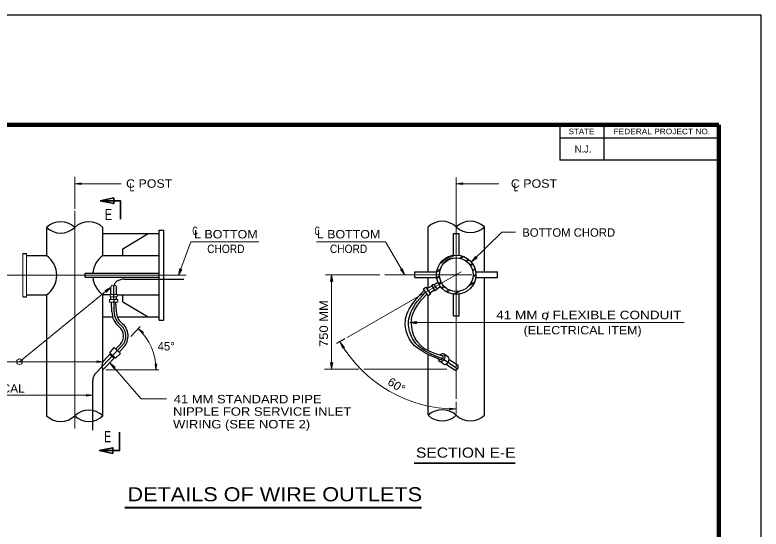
# Model space of a CAD drawing. Extents: x 312601.858 to 312602.699, y 144420.109 to 144420.704.
# Drawn here: x 312602.4337 to 312602.6988, y 144420.5208 to 144420.7035 of the extents above; entities that cross this region are included whole.
import ezdxf
from ezdxf.enums import TextEntityAlignment as Align

# ---------------------------------------------------------------- set-up
doc = ezdxf.new("R2010")
doc.units = 0
doc.header["$LTSCALE"] = 0.0012
doc.linetypes.add('LONG_DASH_SHORT_DASH', pattern=[9.9, 6, -1.2, 1.5, -1.2])
doc.linetypes.add('LONG_DASHED', pattern=[7.5, 6, -1.5])
for name, color, linetype, lineweight in [('1', 7, 'Continuous', 25), ('2', 7, 'Continuous', 25), ('39', 7, 'Continuous', 13), ('61', 7, 'Continuous', 25)]:
    doc.layers.add(name, color=color, linetype=linetype, lineweight=lineweight)

msp = doc.modelspace()

# ---------------------------------------------------------------- hatches: boundary and pattern name
at = {"layer": '39'}
for points in [[(312602.5975, 144420.6173), (312602.5979, 144420.6172), (312602.5959, 144420.6158), (312602.5974, 144420.6177)], [(312602.4926, 144420.613), (312602.493, 144420.6131), (312602.4918, 144420.611), (312602.4923, 144420.6134)], [(312602.5462, 144420.609), (312602.5458, 144420.6088), (312602.5462, 144420.6112), (312602.5466, 144420.6088)], [(312602.5462, 144420.609), (312602.5458, 144420.6088), (312602.5462, 144420.6112), (312602.5466, 144420.6088)], [(312602.5711, 144420.6131), (312602.5713, 144420.6134), (312602.5722, 144420.6112), (312602.5707, 144420.6131)], [(312602.4661, 144420.6054), (312602.4657, 144420.6056), (312602.4678, 144420.6068), (312602.4662, 144420.605)], [(312602.5762, 144420.5942), (312602.5764, 144420.5938), (312602.574, 144420.5942), (312602.5764, 144420.5946)], [(312602.5504, 144420.5853), (312602.5502, 144420.585), (312602.5493, 144420.5872), (312602.5508, 144420.5853)], [(312602.5504, 144420.5853), (312602.5502, 144420.585), (312602.5493, 144420.5872), (312602.5508, 144420.5853)], [(312602.5462, 144420.5798), (312602.5466, 144420.58), (312602.5462, 144420.5776), (312602.5458, 144420.58)], [(312602.5883, 144420.5635), (312602.5881, 144420.5638), (312602.5905, 144420.5635), (312602.5881, 144420.5632)]]:
    msp.add_hatch(color=256, dxfattribs=at).paths.add_polyline_path(points)

# ---------------------------------------------------------------- linework, layer by layer
at = {"layer": '1', "lineweight": 13}
for p, q in [((312602.455, 144420.6346), (312602.455, 144420.646)), ((312602.5905, 144420.6458), (312602.5905, 144420.6341)), ((312602.455, 144420.6435), (312602.4715, 144420.6435)), ((312602.5905, 144420.6435), (312602.6056, 144420.6435)), ((312602.5847, 144420.6151), (312602.5901, 144420.6182)), ((312602.5852, 144420.6158), (312602.5892, 144420.6181)), ((312602.5915, 144420.6171), (312602.5928, 144420.6178)), ((312602.592, 144420.617), (312602.5932, 144420.6177)), ((312602.5939, 144420.6162), (312602.5948, 144420.6167)), ((312602.5942, 144420.6159), (312602.5951, 144420.6165)), ((312602.5954, 144420.6147), (312602.5962, 144420.6152)), ((312602.5956, 144420.6144), (312602.5964, 144420.6149)), ((312602.5441, 144420.6112), (312602.5634, 144420.6112)), ((312602.5462, 144420.5776), (312602.5462, 144420.6112)), ((312602.5836, 144420.6126), (312602.5849, 144420.6133)), ((312602.5836, 144420.6121), (312602.5847, 144420.6128)), ((312602.5963, 144420.6129), (312602.5971, 144420.6134)), ((312602.5963, 144420.6126), (312602.5972, 144420.6131)), ((312602.5965, 144420.6107), (312602.5975, 144420.6113)), ((312602.5836, 144420.6102), (312602.5845, 144420.6108)), ((312602.5836, 144420.6099), (312602.5846, 144420.6104)), ((312602.5842, 144420.6082), (312602.585, 144420.6087)), ((312602.5843, 144420.6079), (312602.5852, 144420.6084)), ((312602.5949, 144420.6071), (312602.5968, 144420.6083)), ((312602.5955, 144420.6078), (312602.5971, 144420.6088)), ((312602.5964, 144420.6103), (312602.5975, 144420.6109)), ((312602.4678, 144420.6068), (312602.4353, 144420.5803)), ((312602.5853, 144420.6066), (312602.5862, 144420.6071)), ((312602.5855, 144420.6063), (312602.5864, 144420.6068)), ((312602.5869, 144420.6052), (312602.5879, 144420.6058)), ((312602.5872, 144420.605), (312602.5883, 144420.6056)), ((312602.5893, 144420.6043), (312602.5909, 144420.6052)), ((312602.5899, 144420.6042), (312602.5918, 144420.6054)), ((312602.4749, 144420.5893), (312602.4782, 144420.5928)), ((312602.574, 144420.5942), (312602.6715, 144420.5942)), ((312602.465, 144420.5803), (312602.4141, 144420.5803)), ((312602.4676, 144420.5798), (312602.4786, 144420.5671)), ((312602.466, 144420.5774), (312602.4848, 144420.5774)), ((312602.5437, 144420.5776), (312602.5559, 144420.5776)), ((312602.5577, 144420.5776), (312602.5872, 144420.5776)), ((312602.4614, 144420.5684), (312602.4104, 144420.5684)), ((312602.4786, 144420.5671), (312602.4876, 144420.5671)), ((312602.5905, 144420.5619), (312602.5905, 144420.566))]:
    msp.add_line(p, q, dxfattribs=at)
at = {"layer": '1', "linetype": 'LONG_DASH_SHORT_DASH', "lineweight": 13}
for p, q in [((312602.455, 144420.5566), (312602.455, 144420.6339)), ((312602.5905, 144420.5671), (312602.5905, 144420.6341)), ((312602.4284, 144420.611), (312602.4945, 144420.611)), ((312602.5517, 144420.5889), (312602.5922, 144420.6122)), ((312602.5651, 144420.6112), (312602.5961, 144420.6112))]:
    msp.add_line(p, q, dxfattribs=at)
at = {"layer": '1'}
for p, q in [((312602.445, 144420.618), (312602.445, 144420.628)), ((312602.465, 144420.618), (312602.465, 144420.628)), ((312602.485, 144420.595), (312602.485, 144420.627)), ((312602.485, 144420.627), (312602.4866, 144420.627)), ((312602.4866, 144420.595), (312602.4866, 144420.627)), ((312602.5805, 144420.6122), (312602.5805, 144420.6282)), ((312602.6005, 144420.6122), (312602.6005, 144420.6282)), ((312602.465, 144420.6258), (312602.485, 144420.6258)), ((312602.472, 144420.6204), (312602.481, 144420.6258)), ((312602.5895, 144420.6258), (312602.5915, 144420.6258)), ((312602.5895, 144420.6181), (312602.5895, 144420.6258)), ((312602.5915, 144420.6181), (312602.5915, 144420.6258)), ((312602.472, 144420.618), (312602.472, 144420.6204)), ((312602.4365, 144420.6187), (312602.4378, 144420.6187)), ((312602.4378, 144420.618), (312602.445, 144420.618)), ((312602.465, 144420.618), (312602.485, 144420.618)), ((312602.4587, 144420.6103), (312602.4587, 144420.6117)), ((312602.4587, 144420.6117), (312602.485, 144420.6117)), ((312602.5758, 144420.6102), (312602.5758, 144420.6122)), ((312602.5758, 144420.6122), (312602.5836, 144420.6122)), ((312602.5974, 144420.6122), (312602.6052, 144420.6122)), ((312602.6052, 144420.6102), (312602.6052, 144420.6122)), ((312602.4587, 144420.6103), (312602.485, 144420.6103)), ((312602.5758, 144420.6102), (312602.5836, 144420.6102)), ((312602.5805, 144420.6065), (312602.5805, 144420.6101)), ((312602.5826, 144420.6076), (312602.5841, 144420.6085)), ((312602.5974, 144420.6102), (312602.6052, 144420.6102)), ((312602.6005, 144420.5613), (312602.6005, 144420.6102)), ((312602.4678, 144420.6042), (312602.4678, 144420.6068)), ((312602.4698, 144420.6042), (312602.4698, 144420.6068)), ((312602.5801, 144420.6063), (312602.5819, 144420.6073)), ((312602.5811, 144420.6048), (312602.5828, 144420.6058)), ((312602.5836, 144420.6062), (312602.5849, 144420.607)), ((312602.4365, 144420.6033), (312602.4378, 144420.6033)), ((312602.4378, 144420.604), (312602.445, 144420.604)), ((312602.445, 144420.5611), (312602.445, 144420.604)), ((312602.465, 144420.5803), (312602.465, 144420.604)), ((312602.4676, 144420.604), (312602.465, 144420.604)), ((312602.4678, 144420.6024), (312602.4678, 144420.6034)), ((312602.4698, 144420.6024), (312602.4698, 144420.6034)), ((312602.47, 144420.604), (312602.485, 144420.604)), ((312602.472, 144420.6016), (312602.472, 144420.604)), ((312602.5805, 144420.5844), (312602.5805, 144420.6037)), ((312602.5895, 144420.5966), (312602.5895, 144420.6043)), ((312602.5915, 144420.5966), (312602.5915, 144420.6043)), ((312602.4682, 144420.598), (312602.468, 144420.6014)), ((312602.4698, 144420.598), (312602.4696, 144420.6014)), ((312602.472, 144420.6016), (312602.481, 144420.5962)), ((312602.465, 144420.5962), (312602.4683, 144420.5962)), ((312602.4702, 144420.5962), (312602.485, 144420.5962)), ((312602.5895, 144420.5966), (312602.5915, 144420.5966)), ((312602.485, 144420.595), (312602.4866, 144420.595)), ((312602.5481, 144420.5869), (312602.551, 144420.5886)), ((312602.4674, 144420.5835), (312602.469, 144420.5853)), ((312602.4712, 144420.5832), (312602.469, 144420.5853)), ((312602.4695, 144420.5848), (312602.4712, 144420.5865)), ((312602.4707, 144420.5837), (312602.4723, 144420.5854)), ((312602.465, 144420.5803), (312602.4677, 144420.5832)), ((312602.465, 144420.5774), (312602.4692, 144420.5818)), ((312602.4695, 144420.5815), (312602.4674, 144420.5835)), ((312602.4689, 144420.5815), (312602.4674, 144420.5829)), ((312602.4695, 144420.5815), (312602.4712, 144420.5832)), ((312602.5805, 144420.5614), (312602.5805, 144420.5828)), ((312602.5877, 144420.5819), (312602.5861, 144420.583)), ((312602.5859, 144420.5795), (312602.5845, 144420.5805)), ((312602.59, 144420.5773), (312602.5867, 144420.5794)), ((312602.5912, 144420.5789), (312602.588, 144420.581)), ((312602.465, 144420.5611), (312602.465, 144420.5774))]:
    msp.add_line(p, q, dxfattribs=at)
at = {"layer": '1', "linetype": 'LONG_DASHED'}
for p, q in [((312602.4727, 144420.6096), (312602.4937, 144420.6096)), ((312602.469, 144420.598), (312602.4689, 144420.6071)), ((312602.4624, 144420.5761), (312602.4718, 144420.586)), ((312602.5904, 144420.5781), (312602.5855, 144420.5814)), ((312602.4614, 144420.556), (312602.4614, 144420.5736))]:
    msp.add_line(p, q, dxfattribs=at)
at = {"layer": '1', "lineweight": 35}
msp.add_line((312602.5755, 144420.5443), (312602.6114, 144420.5443), dxfattribs=at)
at = {"layer": '1', "lineweight": 40}
msp.add_line((312602.4728, 144420.5285), (312602.5782, 144420.5285), dxfattribs=at)
at = {"layer": '1', "lineweight": 13}
for points in [[(312602.4573, 144420.6432), (312602.455, 144420.6435), (312602.4573, 144420.6438), (312602.457, 144420.6435)], [(312602.5928, 144420.6432), (312602.5905, 144420.6435), (312602.5928, 144420.6438), (312602.5925, 144420.6435)], [(312602.4676, 144420.6034), (312602.4676, 144420.6042), (312602.47, 144420.6042), (312602.47, 144420.6034)], [(312602.4673, 144420.6014), (312602.4673, 144420.6024), (312602.4703, 144420.6024), (312602.4703, 144420.6014)], [(312602.479, 144420.5903), (312602.4775, 144420.5921), (312602.4794, 144420.5907), (312602.479, 144420.5907)], [(312602.4628, 144420.5806), (312602.465, 144420.5803), (312602.4628, 144420.58), (312602.463, 144420.5803)], [(312602.4689, 144420.5779), (312602.4676, 144420.5798), (312602.4693, 144420.5783), (312602.4689, 144420.5783)], [(312602.4841, 144420.5796), (312602.4838, 144420.5774), (312602.4835, 144420.5796), (312602.4838, 144420.5794)], [(312602.4592, 144420.5687), (312602.4614, 144420.5684), (312602.4592, 144420.5681), (312602.4594, 144420.5684)]]:
    msp.add_lwpolyline(points, close=True, dxfattribs=at)
for points in [[(312602.6116, 144420.6263), (312602.6067, 144420.6263), (312602.5959, 144420.6158)], [(312602.4365, 144420.6187), (312602.4365, 144420.611), (312602.4365, 144420.6033)], [(312602.4378, 144420.6187), (312602.4378, 144420.611), (312602.4378, 144420.6033)]]:
    msp.add_lwpolyline(points, dxfattribs=at)
at = {"layer": '1'}
for points in [[(312602.5797, 144420.6068), (312602.5814, 144420.6043), (312602.5805, 144420.6037), (312602.5789, 144420.6062)], [(312602.583, 144420.6055), (312602.5818, 144420.6075), (312602.5824, 144420.6079), (312602.5837, 144420.606)]]:
    msp.add_lwpolyline(points, close=True, dxfattribs=at)
for radius in [0.006993, 0.005994]:
    msp.add_circle((312602.590505, 144420.611207), radius, dxfattribs=at)
at = {"layer": '1', "lineweight": 13}
msp.add_circle((312602.435331, 144420.580295), 0.000999, dxfattribs=at)
at = {"layer": '1'}
for centre, radius, start, end in [((312602.449985, 144420.622763), 0.007243, 46.39718, 133.60282), ((312602.459976, 144420.622763), 0.007243, 46.39718, 133.60282), ((312602.58551, 144420.622946), 0.007243, 46.39718, 133.60282), ((312602.595501, 144420.622946), 0.007243, 46.39718, 133.60282), ((312602.449985, 144420.633253), 0.007243, 226.39718, 313.60282), ((312602.595501, 144420.633436), 0.007243, 226.39718, 313.60282), ((312602.439989, 144420.611024), 0.008597, 305.56777, 54.43222), ((312602.469972, 144420.611024), 0.008597, 125.56778, 175.491), ((312602.469972, 144420.611024), 0.008597, 185.49054, 234.43222), ((312602.474962, 144420.598036), 0.006794, 180, 231.58556), ((312602.474962, 144420.598036), 0.005195, 180, 231.58556), ((312602.468134, 144420.589425), 0.004196, 316.46996, 51.58556), ((312602.468134, 144420.589425), 0.005795, 316.46996, 51.58556), ((312602.467247, 144420.578844), 0.002698, 147.47755, 212.52244), ((312602.58551, 144420.556008), 0.007243, 46.39718, 133.60282), ((312602.449985, 144420.566316), 0.007243, 226.39718, 313.60282), ((312602.459976, 144420.555826), 0.007243, 46.39718, 133.60282), ((312602.459976, 144420.566316), 0.007243, 226.39718, 313.60282), ((312602.58551, 144420.566498), 0.007243, 226.39718, 313.60282), ((312602.595501, 144420.566498), 0.007243, 226.39718, 313.60282)]:
    msp.add_arc(centre, radius, start, end, dxfattribs=at)
at = {"layer": '1', "lineweight": 13}
for centre, radius, start, end in [((312602.4688, 144420.606575), 0.001025, 12.68038, 167.31962), ((312602.463595, 144420.577393), 0.020249, 0, 46.47401), ((312602.5905, 144420.6112), 0.0477, 210.19358, 270)]:
    msp.add_arc(centre, radius, start, end, dxfattribs=at)
at = {"layer": '1', "linetype": 'LONG_DASHED'}
for centre, radius, start, end in [((312602.474962, 144420.598036), 0.005994, 180, 231.58556), ((312602.468134, 144420.589425), 0.004995, 316.46996, 51.58556), ((312602.464971, 144420.573622), 0.003597, 136.47905, 180)]:
    msp.add_arc(centre, radius, start, end, dxfattribs=at)
msp.add_ellipse((312602.472662, 144420.607122), major_axis=(-0.003797, 0), ratio=0.657592, start_param=4.712389, end_param=6.2831853, dxfattribs=at)
at = {"layer": '1'}
for centre, major_axis, ratio, start_param, end_param in [((312602.585342, 144420.581716), (0.000852, 0.001233), 0.689333, 2.3424226, 7.5583614), ((312602.585342, 144420.581716), (0.000455, 0.000657), 0.4175, 3.1415927, 6.0947224), ((312602.586772, 144420.580727), (0.000852, 0.001233), 0.689333, 3.1415927, 6.2831853), ((312602.590535, 144420.578125), (0.000568, 0.000822), 0.534, 3.1985105, 6.226976)]:
    msp.add_ellipse(centre, major_axis=major_axis, ratio=ratio, start_param=start_param, end_param=end_param, dxfattribs=at)
for points in [[(312602.585, 144420.581), (312602.5757, 144420.5843), (312602.5716, 144420.5909), (312602.5721, 144420.5987), (312602.5792, 144420.6057)], [(312602.5858, 144420.5823), (312602.5779, 144420.5843), (312602.5738, 144420.5909), (312602.5743, 144420.5987), (312602.5801, 144420.6043)]]:
    msp.add_open_spline(points, degree=3, dxfattribs=at)
at = {"layer": '1', "linetype": 'LONG_DASHED'}
msp.add_open_spline([(312602.5856, 144420.5814), (312602.5769, 144420.5843), (312602.5728, 144420.5909), (312602.5733, 144420.5987), (312602.5796, 144420.605)], degree=3, dxfattribs=at)
at = {"layer": '2', "lineweight": 13}
for q in [(312602.4918, 144420.611), (312602.5204, 144420.6229)]:
    msp.add_line((312602.4962, 144420.6229), q, dxfattribs=at)
msp.add_lwpolyline([(312602.5408, 144420.6229), (312602.5654, 144420.6229), (312602.5722, 144420.6112)], dxfattribs=at)
at = {"layer": '39', "lineweight": 25}
for p, q in [((312601.8578, 144420.7035), (312602.6988, 144420.7035)), ((312602.6988, 144420.1095), (312602.6988, 144420.7035)), ((312602.6988, 144420.1095), (312602.6988, 144420.7035)), ((312602.6988, 144420.1095), (312602.6988, 144420.7035)), ((312602.5735, 144420.6645), (312602.6838, 144420.6645)), ((312602.6838, 144420.6514), (312602.6838, 144420.6645))]:
    msp.add_line(p, q, dxfattribs=at)
at = {"layer": '39', "lineweight": 158}
for p in [(312601.9088, 144420.6645), (312602.6838, 144420.1247)]:
    msp.add_line(p, (312602.6838, 144420.6645), dxfattribs=at)
at = {"layer": '39', "lineweight": 35}
for points in [[(312602.464, 144420.6375), (312602.4688, 144420.6385), (312602.4688, 144420.6365)], [(312602.4637, 144420.5487), (312602.4685, 144420.5477), (312602.4685, 144420.5497)]]:
    msp.add_lwpolyline(points, close=True, dxfattribs=at)
at = {"layer": '39'}
for points in [[(312602.4688, 144420.6365), (312602.464, 144420.6375), (312602.4688, 144420.6385)], [(312602.5975, 144420.6173), (312602.5979, 144420.6172), (312602.5959, 144420.6158), (312602.5974, 144420.6177)], [(312602.4926, 144420.613), (312602.493, 144420.6131), (312602.4918, 144420.611), (312602.4923, 144420.6134)], [(312602.5462, 144420.609), (312602.5458, 144420.6088), (312602.5462, 144420.6112), (312602.5466, 144420.6088)], [(312602.5462, 144420.609), (312602.5458, 144420.6088), (312602.5462, 144420.6112), (312602.5466, 144420.6088)], [(312602.5711, 144420.6131), (312602.5713, 144420.6134), (312602.5722, 144420.6112), (312602.5707, 144420.6131)], [(312602.4661, 144420.6054), (312602.4657, 144420.6056), (312602.4678, 144420.6068), (312602.4662, 144420.605)], [(312602.5762, 144420.5942), (312602.5764, 144420.5938), (312602.574, 144420.5942), (312602.5764, 144420.5946)], [(312602.5504, 144420.5853), (312602.5502, 144420.585), (312602.5493, 144420.5872), (312602.5508, 144420.5853)], [(312602.5504, 144420.5853), (312602.5502, 144420.585), (312602.5493, 144420.5872), (312602.5508, 144420.5853)], [(312602.5462, 144420.5798), (312602.5466, 144420.58), (312602.5462, 144420.5776), (312602.5458, 144420.58)], [(312602.5883, 144420.5635), (312602.5881, 144420.5638), (312602.5905, 144420.5635), (312602.5881, 144420.5632)], [(312602.4685, 144420.5497), (312602.4637, 144420.5487), (312602.4685, 144420.5477)]]:
    msp.add_lwpolyline(points, close=True, dxfattribs=at)
at = {"layer": '39', "lineweight": 35}
for points in [[(312602.4642, 144420.6375), (312602.4712, 144420.6375), (312602.4712, 144420.6309)], [(312602.4639, 144420.5487), (312602.4709, 144420.5487), (312602.4709, 144420.5553)]]:
    msp.add_lwpolyline(points, dxfattribs=at)
at = {"layer": '61'}
for p, q in [((312602.6273, 144420.6645), (312602.6273, 144420.6519)), ((312602.6429, 144420.6645), (312602.6429, 144420.6519)), ((312602.6838, 144420.6597), (312602.6273, 144420.6597)), ((312602.6838, 144420.6519), (312602.6273, 144420.6519))]:
    msp.add_line(p, q, dxfattribs=at)

# ---------------------------------------------------------------- texts
at = {"layer": '1'}
for s, height, width, p in [('L', 0.003, 0.75, (312602.47525, 144420.6408)), ('L', 0.003, 0.75, (312602.61175, 144420.6408)), ('E', 0.004, 0.7, (312602.46695, 144420.6306)), ('41 MM o FLEXIBLE CONDUIT', 0.003, 1.2, (312602.6376, 144420.5954)), ('(ELECTRICAL ITEM)', 0.003, 1.1, (312602.6354, 144420.59)), ('41 MM STANDARD PIPE ', 0.003, 1.15, (312602.51705, 144420.5655)), ('E', 0.004, 0.7, (312602.46665, 144420.5517))]:
    msp.add_text(s, height=height, dxfattribs=dict(at, width=width)).set_placement(p, align=Align.CENTER)
for s, p in [('BOTTOM CHORD', (312602.63045, 144420.6247)), ('45°', (312602.48745, 144420.5843))]:
    msp.add_text(s, height=0.003, dxfattribs=at).set_placement(p, align=Align.CENTER)
at = {"layer": '1', "width": 1.05}
msp.add_text('60°', height=0.003, rotation=326.865, dxfattribs=at).set_placement((312602.56848, 144420.570663), align=Align.CENTER)
at = {"layer": '1'}
for s, width, p in [('ELECTRICAL', 1.05, (312602.4112, 144420.5693)), ('NIPPLE FOR SERVICE INLET', 1.15, (312602.4899, 144420.5611)), ('WIRING (SEE NOTE 2)', 1.15, (312602.4899, 144420.5566))]:
    msp.add_text(s, height=0.003, dxfattribs=dict(at, width=width)).set_placement(p)
at = {"layer": '2'}
for s, height, width, p in [('C POST', 0.003, 1.1, (312602.4732, 144420.6421)), ('C POST', 0.003, 1.1, (312602.6099, 144420.6421)), ('SECTION E-E', 0.0036, 1.15, (312602.5762, 144420.5462)), ('DETAILS OF WIRE OUTLETS', 0.005, 1.15, (312602.4737, 144420.5307))]:
    msp.add_text(s, height=height, dxfattribs=dict(at, width=width)).set_placement(p)
for s, width, p in [('C', 0.6, (312602.4977, 144420.6253)), ('L BOTTOM', 1.1, (312602.50865, 144420.6241)), ('C', 0.6, (312602.5411, 144420.6253)), ('L BOTTOM', 1.1, (312602.55225, 144420.6241)), ('CHORD', 0.9, (312602.50865, 144420.6189)), ('CHORD', 0.9, (312602.55225, 144420.6189))]:
    msp.add_text(s, height=0.003, dxfattribs=dict(at, width=width)).set_placement(p, align=Align.CENTER)
at = {"layer": '2', "width": 1.15}
msp.add_text('750 MM', height=0.003, rotation=90, dxfattribs=at).set_placement((312602.5449, 144420.59385), align=Align.CENTER)
at = {"layer": '2'}
msp.add_text('/', height=0.003, dxfattribs=at).set_placement((312602.62285, 144420.595), align=Align.CENTER)
at = {"layer": '61'}
for s, width, p in [('STATE', 1.05, (312602.635, 144420.6611)), ('FEDERAL PROJECT NO.', 1.1, (312602.66355, 144420.6611))]:
    msp.add_text(s, height=0.00201, dxfattribs=dict(at, width=width)).set_placement(p, align=Align.CENTER)
msp.add_text('N.J.', height=0.002512, dxfattribs=at).set_placement((312602.63555, 144420.6546), align=Align.CENTER)

doc.saveas('drawing.dxf')
